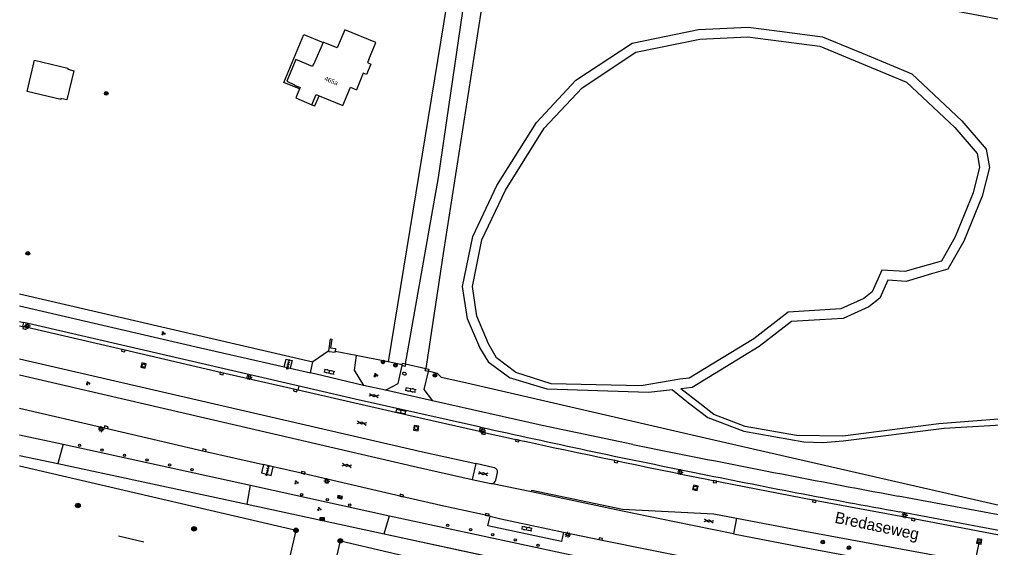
# Model space of a CAD drawing. Extents: x 128999 to 131010, y 395498 to 399007.
# Drawn here: x 129000 to 129211.4, y 397059.8 to 397174.6 of the extents above; entities that cross this region are included whole.
import ezdxf

# ---------------------------------------------------------------- set-up
doc = ezdxf.new("R2010")
doc.units = 0
for name, color, linetype in [('bs-afsc-ballenvanger', 7, 'Continuous'), ('bs-afsc-belijning', 7, 'Continuous'), ('bs-afsc-doel', 7, 'Continuous'), ('bs-symb-cornervlag', 7, 'Continuous'), ('bs-symb-sproeier', 7, 'Continuous'), ('gg-afsc-hekwerk', 7, 'Continuous'), ('gg-afsc-muur', 7, 'Continuous'), ('gg-anno-huisnummerreeks BGT', 7, 'Continuous'), ('gg-anno-openbare ruimte label', 7, 'Continuous'), ('gg-bbg-bijgebouw', 7, 'Continuous'), ('gg-bbg-hoofdgebouw', 7, 'Continuous'), ('gg-bbg-luifel en loopbrug', 7, 'Continuous'), ('gg-bbg-onder overbouw', 7, 'Continuous'), ('gg-bbg-pand overbouw', 7, 'Continuous'), ('gg-knt-onverhard', 7, 'Continuous'), ('gg-knt-verharding', 7, 'Continuous'), ('gg-kwrk-duiker nz buis', 7, 'Continuous'), ('gt-grn-groengrens', 7, 'Continuous'), ('gt-grn-vlakafsluiter', 7, 'Continuous'), ('gt-grn-weggrens', 7, 'Continuous'), ('gt-symb-boom', 7, 'Continuous'), ('gt-symb-brandkraan', 7, 'Continuous'), ('gt-symb-gesloten verharding', 7, 'Continuous'), ('gt-symb-groenvak', 7, 'Continuous'), ('gt-symb-kast', 7, 'Continuous'), ('gt-symb-klinker verharding', 7, 'Continuous'), ('gt-symb-kolk', 7, 'Continuous'), ('gt-symb-lichtmast', 7, 'Continuous'), ('gt-symb-rioolschacht', 7, 'Continuous'), ('gt-symb-tegel verharding', 7, 'Continuous'), ('gt-symb-verkeersregelinstallatiekast', 7, 'Continuous'), ('gt-symb-vlaggenmast', 7, 'Continuous')]:
    doc.layers.add(name, color=color, linetype=linetype)

# ---------------------------------------------------------------- blocks, each defined once
blk = doc.blocks.new('gt0-RS')
at = {"layer": 'gt-symb-rioolschacht'}
blk.add_lwpolyline([(-0.5, -0.5), (0.5, -0.5), (0.5, 0.5), (-0.5, 0.5)], close=True, dxfattribs=at)
blk.add_circle((0, 0), 0.375, dxfattribs=at)
blk = doc.blocks.new('gt0-KOLK')
at = {"layer": 'gt-symb-kolk'}
blk.add_lwpolyline([(0, 0), (0.38, 0), (0.38, 0.4), (-0.38, 0.4), (-0.38, 0), (0, 0)], dxfattribs=at)
blk = doc.blocks.new('gt0-GESVH1')
at = {"layer": 'gt-symb-gesloten verharding'}
for p, q in [((-0.99, -0.26), (0.01, 0.24)), ((0.01, -0.26), (-0.99, 0.24)), ((0.01, 0.24), (1.01, -0.26)), ((1.01, 0.24), (0.01, -0.26))]:
    blk.add_line(p, q, dxfattribs=at)
blk = doc.blocks.new('gt0-LMAST')
at = {"layer": 'gt-symb-lichtmast'}
for p, q in [((-0.18, 0.17), (-0.45, 0.44)), ((-0.01, 0.25), (-0.01, 0.62)), ((0.17, 0.17), (0.44, 0.44)), ((-0.26, 0), (-0.63, 0)), ((-0.18, -0.18), (-0.45, -0.45)), ((-0.01, -0.25), (-0.01, -0.63)), ((0.44, -0.45), (0.17, -0.18)), ((0.24, 0), (0.62, 0))]:
    blk.add_line(p, q, dxfattribs=at)
blk.add_circle((-0.01, 0), 0.25, dxfattribs=at)
blk = doc.blocks.new('gt0-GRVAK')
at = {"layer": 'gt-symb-groenvak'}
for p, q in [((-0.11, 0.19), (-0.23, 0.24)), ((-0.18, 0.15), (0.09, 0.15)), ((-0.09, 0.21), (-0.16, 0.32)), ((-0.05, 0.21), (-0.05, 0.39)), ((0, 0.21), (0.06, 0.32)), ((0.01, 0.19), (0.13, 0.24)), ((0.26, -0.05), (0.2, 0.06)), ((0.31, -0.05), (0.31, 0.13)), ((0.35, -0.05), (0.41, 0.06)), ((-0.24, -0.23), (-0.36, -0.18)), ((-0.32, -0.26), (-0.05, -0.26)), ((-0.23, -0.21), (-0.29, -0.1)), ((-0.18, -0.2), (-0.18, -0.02)), ((-0.14, -0.21), (-0.07, -0.1)), ((-0.12, -0.23), (0, -0.18)), ((0.24, -0.07), (0.12, -0.02)), ((0.17, -0.11), (0.44, -0.11)), ((0.37, -0.07), (0.49, -0.02))]:
    blk.add_line(p, q, dxfattribs=at)
blk = doc.blocks.new('gt0-VMAST')
at = {"layer": 'gt-symb-vlaggenmast'}
blk.add_circle((0, 0), 0.25, dxfattribs=at)
blk = doc.blocks.new('gt0-KAST')
at = {"layer": 'gt-symb-kast'}
for p, q in [((-0.5, -0.25), (0.5, 0.25)), ((-0.5, 0.25), (0.5, -0.25))]:
    blk.add_line(p, q, dxfattribs=at)
blk.add_lwpolyline([(0.5, 0.25), (-0.5, 0.25), (-0.5, -0.25), (0.5, -0.25)], close=True, dxfattribs=at)
blk = doc.blocks.new('gt0-VRIKST')
at = {"layer": 'gt-symb-verkeersregelinstallatiekast'}
for p, q in [((-0.5, -0.25), (0.5, 0.25)), ((-0.5, 0.25), (0.5, -0.25))]:
    blk.add_line(p, q, dxfattribs=at)
blk.add_lwpolyline([(0.5, 0.25), (-0.5, 0.25), (-0.5, -0.25), (0.5, -0.25)], close=True, dxfattribs=at)
blk = doc.blocks.new('gt0-KL1')
at = {"layer": 'gt-symb-klinker verharding'}
for p, q in [((-1.15, 0.3), (1.15, 0.3)), ((-1, -0.3), (-1, 0.3)), ((-0.5, 0.3), (-0.5, 0.45)), ((0, -0.3), (0, 0.3)), ((0.5, 0.3), (0.5, 0.45)), ((1, -0.3), (1, 0.3)), ((-1.15, -0.3), (1.15, -0.3)), ((-0.5, -0.45), (-0.5, -0.3)), ((0.5, -0.45), (0.5, -0.3))]:
    blk.add_line(p, q, dxfattribs=at)
blk = doc.blocks.new('bs0-CORNVLG')
at = {"layer": 'bs-symb-cornervlag'}
for p, q in [((-0.34, 0.2), (0.2, -0.34)), ((-0.21, 0.35), (0.34, -0.2)), ((0.03, 0.4), (0.4, 0.03)), ((-0.4, -0.03), (-0.03, -0.4))]:
    blk.add_line(p, q, dxfattribs=at)
blk.add_circle((0, 0), 0.5, dxfattribs=at)
blk = doc.blocks.new('bs0-SPROEIER')
at = {"layer": 'bs-symb-sproeier'}
for p, q in [((-0.34, 0.2), (0.2, -0.34)), ((-0.21, 0.35), (0.34, -0.2)), ((0.03, 0.4), (0.4, 0.03)), ((-0.4, -0.03), (-0.03, -0.4))]:
    blk.add_line(p, q, dxfattribs=at)
blk.add_circle((0, 0), 0.5, dxfattribs=at)
blk = doc.blocks.new('gt0-BOOM')
at = {"layer": 'gt-symb-boom'}
for radius in [0.4, 0.2]:
    blk.add_circle((0, 0), radius, dxfattribs=at)
blk = doc.blocks.new('gt0-BR')
at = {"layer": 'gt-symb-brandkraan'}
for centre, radius, start, end in [((-0.24, 0), 0.206, 107.5669, 252.4331), ((0.6, -2.66), 3, 106.892, 107.5669), ((0, -0.69), 0.938, 73.108, 106.892), ((-0.6, -2.66), 3, 72.4331, 73.108), ((0.24, 0), 0.206, 287.567, 72.4331), ((0.6, 2.66), 3, 252.4331, 253.108), ((0, 0.69), 0.938, 253.108, 286.8921), ((-0.6, 2.66), 3, 286.8921, 287.567)]:
    blk.add_arc(centre, radius, start, end, dxfattribs=at)
blk = doc.blocks.new('gt0-TEG1')
at = {"layer": 'gt-symb-tegel verharding'}
for p, q in [((-1.12, 0), (1.12, 0)), ((-0.9, -0.25), (-0.9, 0.25)), ((-0.45, -0.25), (-0.45, 0.25)), ((0, -0.25), (0, 0.25)), ((0.45, -0.25), (0.45, 0.25)), ((0.9, -0.25), (0.9, 0.25))]:
    blk.add_line(p, q, dxfattribs=at)

msp = doc.modelspace()

# ---------------------------------------------------------------- linework, layer by layer
at = {"layer": 'bs-afsc-ballenvanger'}
msp.add_lwpolyline([(129000, 397079.82), (129008.34, 397078.06), (129049.59, 397069.18), (129079.4, 397062.77), (129120.18, 397053.98), (129139.89, 397049.77)], dxfattribs=at)
at = {"layer": 'bs-afsc-belijning'}
for points in [[(129000, 396954.32), (129033.11, 396946.66), (129060.2, 397063.52), (129000, 397077.45)], [(129069.85, 397061.25), (129133.01, 397046.45), (129106, 396929.79), (129042.52, 396944.48), (129069.85, 397061.25)]]:
    msp.add_lwpolyline(points, dxfattribs=at)
at = {"layer": 'bs-afsc-doel'}
msp.add_line((129027.09, 397060.97), (129021.56, 397062.28), dxfattribs=at)
at = {"layer": 'gg-afsc-hekwerk'}
for p, q in [((129000, 397114.95), (129063.87, 397100.18)), ((129000, 397114.95), (129063.87, 397100.18)), ((129067.34, 397102.56), (129063.87, 397100.18)), ((129067.34, 397102.56), (129063.87, 397100.18)), ((129073.29, 397101.52), (129068.72, 397102.43)), ((129073.29, 397101.52), (129068.72, 397102.43)), ((129080.26, 397100.13), (129073.29, 397101.52)), ((129080.26, 397100.13), (129073.29, 397101.52)), ((129083.32, 397099.52), (129080.26, 397100.13)), ((129000, 397079.82), (129008.34, 397078.06)), ((129008.34, 397078.06), (129049.59, 397069.18)), ((129049.59, 397069.18), (129079.4, 397062.77)), ((129079.4, 397062.77), (129120.18, 397053.98))]:
    msp.add_line(p, q, dxfattribs=at)
for points in [[(129088.99, 397098.23), (129090.94, 397097.73), (129091.78, 397096.85), (129096.44, 397095.78)], [(129096.44, 397095.78), (129150.23, 397083.43), (129223.38, 397066.69)]]:
    msp.add_lwpolyline(points, dxfattribs=at)
at = {"layer": 'gg-afsc-muur'}
for p, q in [((129083.29, 397099.33), (129083.32, 397099.52)), ((129088.99, 397098.23), (129088.95, 397098.03))]:
    msp.add_line(p, q, dxfattribs=at)
for points in [[(129067.34, 397102.56), (129067.69, 397105.14), (129068, 397105.1), (129067.74, 397103.17), (129068.8, 397103.03), (129068.72, 397102.43)], [(129067.34, 397102.56), (129067.32, 397102.42), (129068.69, 397102.23), (129068.72, 397102.43)], [(129084.04, 397099.71), (129083.93, 397099.18), (129083.29, 397099.33)], [(129083.32, 397099.52), (129083.39, 397099.84), (129084.04, 397099.71)], [(129088.95, 397098.03), (129088.31, 397098.19), (129088.44, 397098.72)], [(129088.44, 397098.72), (129089.08, 397098.56), (129088.99, 397098.23)]]:
    msp.add_lwpolyline(points, dxfattribs=at)
at = {"layer": 'gg-bbg-bijgebouw'}
msp.add_lwpolyline([(129011.82, 397163.47), (129010.34, 397157.16), (129009.03, 397157.45), (129008.98, 397157.2), (129003.18, 397158.57), (129001.65, 397158.93), (129003.27, 397165.78), (129010.57, 397164.03), (129010.51, 397163.78), (129011.82, 397163.47)], dxfattribs=at)
at = {"layer": 'gg-bbg-hoofdgebouw'}
msp.add_line((129065.21, 397158.03), (129070.42, 397155.89), dxfattribs=at)
for points in [[(129070.8, 397172.38), (129069.17, 397168.41), (129066.11, 397169.66), (129066.08, 397169.58)], [(129076.03, 397165.91), (129077.55, 397169.6), (129070.8, 397172.38)], [(129066.08, 397169.58), (129064.04, 397164.79), (129063.95, 397164.83), (129063.76, 397164.38), (129060.17, 397165.89), (129058.17, 397161.16), (129059.89, 397160.41), (129059.85, 397160.32), (129061.07, 397159.82), (129060.93, 397159.49)], [(129076.03, 397165.91), (129075.75, 397165.22), (129076.49, 397164.91), (129075.56, 397162.64), (129074.81, 397162.94), (129073.33, 397159.34)], [(129070.42, 397155.89), (129072.06, 397159.87), (129073.33, 397159.34)], [(129060.93, 397159.49), (129060.13, 397157.56), (129063.66, 397156.08)]]:
    msp.add_lwpolyline(points, dxfattribs=at)
at = {"layer": 'gg-bbg-luifel en loopbrug'}
msp.add_lwpolyline([(129060.93, 397159.49), (129057.56, 397160.9), (129061.93, 397171.35), (129066.08, 397169.58)], dxfattribs=at)
at = {"layer": 'gg-bbg-onder overbouw'}
msp.add_lwpolyline([(129063.66, 397156.08), (129064.57, 397158.29), (129065.21, 397158.03)], dxfattribs=at)
at = {"layer": 'gg-bbg-pand overbouw'}
msp.add_lwpolyline([(129063.66, 397156.08), (129064.3, 397155.82), (129065.21, 397158.03)], dxfattribs=at)
at = {"layer": 'gg-knt-onverhard'}
for points in [[(129084.04, 397099.71), (129091.22, 397140.22), (129098.74, 397191.88), (129101.91, 397200.17), (129105.85, 397227.08), (129112.07, 397274.77), (129114.37, 397277.2), (129119.28, 397279.17), (129124.34, 397279.43), (129128.93, 397278.58), (129128.85, 397271.23), (129121.25, 397274.76), (129119.32, 397273.94), (129116.92, 397271.39), (129115.72, 397266.86), (129106.31, 397200.76)], [(129224.91, 397172.42), (129125.9, 397191.16), (129113.45, 397193.52), (129106.57, 397194.04), (129102.52, 397189.83), (129101.77, 397185.03), (129092.34, 397124.65), (129088.44, 397098.72)], [(129100.19, 397103.25), (129097.55, 397109.49), (129096.44, 397116.57), (129098.66, 397127.39), (129103.93, 397138.49), (129112.53, 397152.23), (129121.13, 397161.39), (129133.33, 397169.43), (129147.81, 397172.44), (129158.59, 397172.91), (129165.4, 397172.04), (129174.77, 397170.84), (129184.5, 397166.81), (129194.22, 397162.77), (129205.12, 397152.56), (129210.43, 397146.37), (129211.15, 397142.41), (129209.56, 397136.22), (129205.59, 397126.41), (129202.1, 397120.3), (129198.53, 397119.27), (129192.97, 397117.66), (129189.03, 397117.92), (129187.28, 397114.04), (129184.9, 397112.14), (129179.28, 397109.6), (129174.21, 397109.28), (129168.08, 397108.9), (129161.01, 397103.46), (129146.44, 397094.58), (129143.97, 397094.29)], [(129143.73, 397096.37), (129135.32, 397094.94), (129115.76, 397095.39), (129108.01, 397097.84), (129103.85, 397101.05), (129102.12, 397104.07), (129099.59, 397110.07), (129098.58, 397116.52), (129100.67, 397126.72), (129105.77, 397137.48), (129114.2, 397150.94), (129122.49, 397159.77), (129134.15, 397167.46), (129148.07, 397170.35), (129158.5, 397170.81), (129174.23, 397168.8), (129193.06, 397160.98), (129203.61, 397151.1), (129208.47, 397145.44), (129209, 397142.49), (129207.57, 397136.88), (129203.69, 397127.32), (129200.7, 397122.08), (129192.74, 397119.78), (129187.71, 397120.11), (129185.58, 397115.36), (129183.8, 397113.94), (129178.77, 397111.67), (129167.31, 397110.95), (129159.83, 397105.19), (129145.74, 397096.61), (129143.73, 397096.37)], [(129142.13, 397094.08), (129136.93, 397093.47), (129114.83, 397094.2), (129106.68, 397096.66), (129102.24, 397099.92), (129100.19, 397103.25)], [(129237.19, 397089.55), (129200.09, 397086.67), (129179.24, 397084), (129169.15, 397084.15), (129157.97, 397086.09), (129151.17, 397088.74), (129148.1, 397091.13), (129143.97, 397094.29)], [(129142.13, 397094.08), (129145.61, 397091.22), (129149.87, 397088.04), (129157.65, 397085.12), (129170.74, 397082.8), (129174.93, 397082.6), (129179.28, 397082.98), (129201.29, 397085.76), (129232.33, 397087.53), (129236.1, 397085.5)]]:
    msp.add_lwpolyline(points, dxfattribs=at)
at = {"layer": 'gg-knt-verharding'}
for p, q in [((129000, 397108.93), (129000.95, 397108.71)), ((129000, 397107.97), (129000.71, 397107.81)), ((129000.71, 397107.81), (129000.95, 397108.71)), ((129060.87, 397094.84), (129000.95, 397108.71)), ((129057.63, 397099.05), (129058.96, 397098.75)), ((129058.96, 397098.75), (129063.37, 397097.74)), ((129063.37, 397097.74), (129063.87, 397100.18)), ((129060.69, 397094), (129060.87, 397094.84)), ((129079.65, 397093.99), (129074.9, 397095.05)), ((129089.92, 397091.67), (129079.65, 397093.99)), ((129100.16, 397085.03), (129100.38, 397085.98)), ((129100.16, 397085.03), (129108.41, 397083.21)), ((129055.23, 397077.32), (129053.11, 397077.81)), ((129099.32, 397078.05), (129098.57, 397074.59)), ((129103.33, 397077.14), (129099.32, 397078.05)), ((129103.69, 397074.45), (129104.04, 397076.08)), ((129098.57, 397074.59), (129102.6, 397073.72)), ((129217.73, 397066), (129191.26, 397070.96)), ((129225.53, 397061.18), (129191.54, 397067.57)), ((129156.09, 397066.2), (129155.39, 397062.79))]:
    msp.add_line(p, q, dxfattribs=at)
for points in [[(129000, 397112.37), (129039.44, 397103.21), (129057.63, 397099.05)], [(129060.69, 397094), (129044.06, 397097.8), (129022.66, 397102.79), (129000.71, 397107.81)], [(129000, 397100.82), (129087.7, 397080.61), (129099.32, 397078.05)], [(129057.63, 397099.05), (129058.04, 397100.74), (129059.33, 397100.42), (129058.96, 397098.75)], [(129073.29, 397101.52), (129072.89, 397098.34), (129074.9, 397095.05)], [(129079.65, 397093.99), (129082.4, 397095.48), (129083.29, 397099.33)], [(129000, 397097.36), (129086.66, 397077.24), (129098.57, 397074.59)], [(129074.9, 397095.05), (129066.12, 397097.11), (129063.37, 397097.74)], [(129088.95, 397098.03), (129088.05, 397094.17), (129089.92, 397091.67)], [(129100.38, 397085.98), (129073.06, 397092.02), (129060.87, 397094.84)], [(129100.16, 397085.03), (129086.95, 397087.98), (129060.69, 397094)], [(129000, 397090.09), (129018.82, 397085.74), (129040.22, 397080.75), (129053.11, 397077.81)], [(129133.51, 397082.21), (129113.79, 397086.35), (129089.92, 397091.67)], [(129053.11, 397077.81), (129052.66, 397076.01), (129054.78, 397075.48), (129055.23, 397077.32)], [(129102.44, 397066.59), (129091.74, 397068.94), (129083.16, 397070.89), (129061.7, 397075.85), (129055.23, 397077.32)], [(129149.94, 397074.56), (129173.06, 397070.06), (129194.59, 397066.08), (129216.26, 397061.99)], [(129111.48, 397071.87), (129111.55, 397072.27), (129131.29, 397068.1), (129151.15, 397067.14), (129156.09, 397066.2)], [(129155.39, 397062.79), (129142.55, 397065.35), (129131.23, 397067.68), (129111.48, 397071.87)], [(129118.45, 397063.15), (129118.01, 397061.08), (129101.98, 397064.53), (129102.44, 397066.59)], [(129102.44, 397066.59), (129104.81, 397066.06), (129118.45, 397063.15)], [(129156.09, 397066.2), (129170.95, 397063.32), (129207.94, 397056.5)], [(129118.45, 397063.15), (129126.46, 397061.46), (129148.85, 397056.94)], [(129155.39, 397062.79), (129170.08, 397059.93), (129196.82, 397054.97), (129207.21, 397053.02)]]:
    msp.add_lwpolyline(points, dxfattribs=at)
for centre, radius, start, end in [((129539.52, 399043.91), 2006.57, 257.35844, 258.71798), ((129808.07, 400338.75), 3329.87, 257.87084, 258.60085), ((129852.83, 400623.74), 3613.84, 258.51875, 259.45154), ((129103.16, 397076.25), 0.897, 348.8284, 79.1263), ((129529.22, 398951.85), 1914.3, 258.48115, 259.83972), ((129102.77, 397074.65), 0.941, 259.9125, 347.9537)]:
    msp.add_arc(centre, radius, start, end, dxfattribs=at)
at = {"layer": 'gg-kwrk-duiker nz buis'}
msp.add_line((129208.91, 397061.11), (129199.74, 397017.48), dxfattribs=at)
at = {"layer": 'gt-grn-groengrens'}
for p, q in [((129000, 397084.29), (129009.54, 397082.26)), ((129009.54, 397082.26), (129008.34, 397078.06)), ((129009.54, 397082.26), (129050.3, 397073.34)), ((129049.59, 397069.18), (129050.3, 397073.34)), ((129050.3, 397073.34), (129080.58, 397066.68)), ((129079.4, 397062.77), (129080.58, 397066.68)), ((129080.58, 397066.68), (129121.1, 397057.97))]:
    msp.add_line(p, q, dxfattribs=at)
msp.add_lwpolyline([(129110.94, 397323.77), (129097.96, 397240.33), (129103.04, 397239.26), (129080.26, 397100.13)], dxfattribs=at)
at = {"layer": 'gt-grn-vlakafsluiter'}
msp.add_line((129084.04, 397099.71), (129088.44, 397098.72), dxfattribs=at)
at = {"layer": 'gt-grn-weggrens'}
msp.add_line((129111.48, 397071.87), (129102.6, 397073.72), dxfattribs=at)

# ---------------------------------------------------------------- block references
at = {"layer": 'bs-symb-cornervlag'}
for p in [(129060.2, 397063.52), (129069.85, 397061.25)]:
    msp.add_blockref('bs0-CORNVLG', p, dxfattribs=at)
at = {"layer": 'bs-symb-sproeier'}
for p in [(129012.73, 397068.92), (129038.01, 397063.84)]:
    msp.add_blockref('bs0-SPROEIER', p, dxfattribs=at)
at = {"layer": 'gt-symb-boom'}
for p in [(129018.9, 397158.53), (129001.83, 397123.75), (129079.14, 397100.14), (129081.83, 397099.43), (129090.42, 397097.22), (129174.86, 397060.96), (129180.55, 397059.73)]:
    msp.add_blockref('gt0-BOOM', p, dxfattribs=at)
at = {"layer": 'gt-symb-brandkraan', "rotation": -12.056992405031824}
msp.add_blockref('gt0-BR', (129083.78, 397097.59), dxfattribs=at)
at = {"layer": 'gt-symb-gesloten verharding'}
for p, rotation in [((129077.16, 397092.82), -9.905079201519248), ((129074.5, 397086.85), -9.905079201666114), ((129071.26, 397077.64), -9.905079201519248), ((129100.93, 397075.86), -9.905079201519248), ((129150.05, 397065.55), -9.905079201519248)]:
    msp.add_blockref('gt0-GESVH1', p, dxfattribs=dict(at, rotation=rotation))
at = {"layer": 'gt-symb-groenvak'}
for p in [(129031.33, 397106.34), (129077.52, 397097.21), (129077.57, 397097.3), (129014.92, 397095.51), (129060.27, 397073.96), (129065.25, 397068.17)]:
    msp.add_blockref('gt0-GRVAK', p, dxfattribs=at)
at = {"layer": 'gt-symb-kast'}
msp.add_blockref('gt0-KAST', (129065.88, 397065.96), dxfattribs=at)
at = {"layer": 'gt-symb-klinker verharding', "rotation": -11.534620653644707}
for p in [(129067.47, 397098.03), (129085.15, 397094.06), (129083.04, 397089.38), (129110.44, 397063.92)]:
    msp.add_blockref('gt0-KL1', p, dxfattribs=at)
at = {"layer": 'gt-symb-kolk'}
for p, rotation in [((129001.19, 397107.7), 167.11668164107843), ((129022.66, 397102.79), 166.88562402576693), ((129044.06, 397097.8), 167.10881490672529), ((129060.09, 397094.13), 164.73851171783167), ((129018.82, 397085.74), -13.131926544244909), ((129101.06, 397084.83), 167.5884831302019), ((129108.41, 397083.21), 167.54734270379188), ((129040.22, 397080.75), -12.857919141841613), ((129129.88, 397078.67), 168.24849944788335), ((129061.7, 397075.85), -13.006713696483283), ((129151.45, 397074.28), 169.26930460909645), ((129083.16, 397070.89), -12.76777946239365), ((129173.06, 397070.06), 168.94804793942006), ((129101.76, 397066.74), -12.552441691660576), ((129194.59, 397066.08), 169.5399688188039), ((129126.46, 397061.46), -11.404887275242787)]:
    msp.add_blockref('gt0-KOLK', p, dxfattribs=dict(at, rotation=rotation))
at = {"layer": 'gt-symb-lichtmast'}
for p in [(129001.77, 397107.99), (129050.04, 397096.86), (129017.79, 397085.53), (129100.88, 397085.18), (129143.84, 397076.19), (129066.91, 397074.23), (129192.71, 397066.8), (129119.34, 397062.56)]:
    msp.add_blockref('gt0-LMAST', p, dxfattribs=at)
at = {"layer": 'gt-symb-rioolschacht'}
for p, rotation in [((129027.02, 397099.35), -12.609332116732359), ((129086.36, 397085.76), -8.276183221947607), ((129147.12, 397072.77), 75.95592790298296), ((129208.91, 397061.11), 78.36404125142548)]:
    msp.add_blockref('gt0-RS', p, dxfattribs=dict(at, rotation=rotation))
at = {"layer": 'gt-symb-tegel verharding'}
for p, rotation in [((129058.53, 397099.57), 77.17287657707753), ((129054.02, 397076.44), 77.17287657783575)]:
    msp.add_blockref('gt0-TEG1', p, dxfattribs=dict(at, rotation=rotation))
at = {"layer": 'gt-symb-verkeersregelinstallatiekast', "rotation": -12.924451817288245}
msp.add_blockref('gt0-VRIKST', (129069.75, 397070.73), dxfattribs=at)
at = {"layer": 'gt-symb-vlaggenmast'}
for p in [(129013.08, 397082.03), (129017.97, 397080.98), (129022.87, 397079.86), (129027.77, 397078.84), (129032.7, 397077.75), (129037.59, 397076.69), (129061.41, 397071.3), (129067.01, 397070.17), (129071.89, 397069.01), (129093.2, 397064.62), (129098.2, 397063.66), (129103.02, 397062.57), (129107.93, 397061.44), (129112.88, 397060.29)]:
    msp.add_blockref('gt0-VMAST', p, dxfattribs=at)

# ---------------------------------------------------------------- texts
at = {"layer": 'gg-anno-huisnummerreeks BGT'}
msp.add_text('465a', height=1, rotation=337.7, dxfattribs=at).set_placement((129066.27, 397161.38))
at = {"layer": 'gg-anno-openbare ruimte label'}
msp.add_text('Bredaseweg', height=2.5, rotation=348.3, dxfattribs=at).set_placement((129177.31, 397065.18))

doc.saveas('drawing.dxf')
